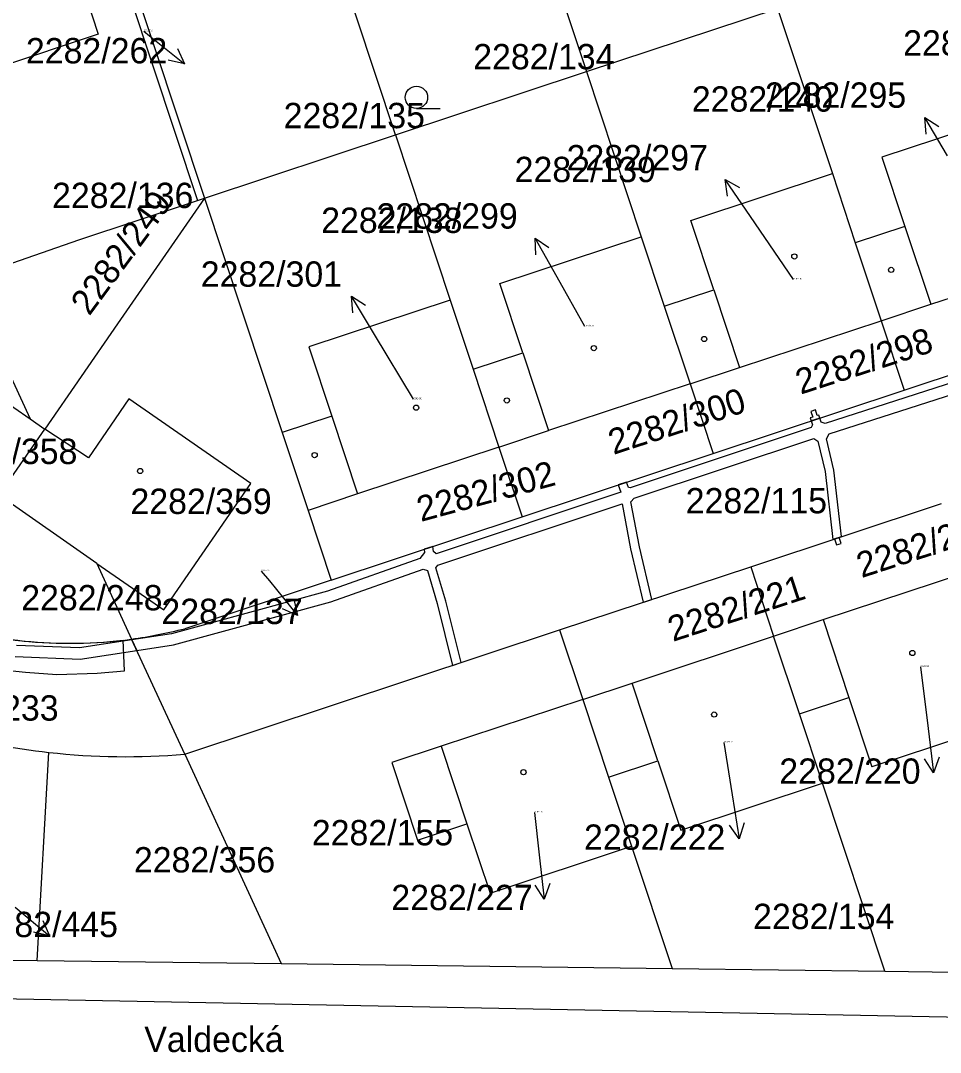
# Model space of a CAD drawing. Extents: x -785744 to -782822, y -1067550 to -1063910.
# Drawn here: x -783802 to -783740.2, y -1066179 to -1066109.7 of the extents above; entities that cross this region are included whole.
import ezdxf

# ---------------------------------------------------------------- set-up
doc = ezdxf.new("R2010")
doc.units = 0
for name, color, linetype in [('Hranice parcel', 7, 'Continuous'), ('Parcelní čísla', 7, 'Continuous'), ('Pop_ČP_popisy', 7, 'Continuous'), ('Vnitřní kresba', 7, 'Continuous'), ('Věcná břemena k části', 7, 'Continuous'), ('Značky budov', 7, 'Continuous'), ('Značky kultur', 7, 'Continuous')]:
    doc.layers.add(name, color=color, linetype=linetype)

msp = doc.modelspace()

# ---------------------------------------------------------------- linework, layer by layer
at = {"layer": 'Hranice parcel'}
for p, q in [((-783798.58, -1066096.16), (-783790.08, -1066121.79)), ((-783767.98, -1066101.08), (-783763.99, -1066113.13)), ((-783799.66, -1066101.8), (-783796.75, -1066110.63)), ((-783751.17, -1066108.89), (-783747.49, -1066119.98)), ((-783796.75, -1066110.63), (-783806.14, -1066113.74)), ((-783763.99, -1066113.13), (-783760.31, -1066124.22)), ((-783734.68, -1066115.74), (-783744.16, -1066118.88)), ((-783744.16, -1066118.88), (-783742.62, -1066123.53)), ((-783756.98, -1066123.12), (-783747.49, -1066119.98)), ((-783798.05, -1066124.42), (-783790.08, -1066121.79)), ((-783789.61, -1066121.63), (-783795.45, -1066130.06)), ((-783790.08, -1066121.79), (-783789.61, -1066121.63)), ((-783789.61, -1066121.63), (-783784.4, -1066137.36)), ((-783755.44, -1066127.77), (-783756.98, -1066123.12)), ((-783769.8, -1066127.36), (-783760.31, -1066124.22)), ((-783805.49, -1066127), (-783798.05, -1066124.42)), ((-783740.89, -1066128.75), (-783731.4, -1066125.61)), ((-783805.65, -1066127.05), (-783801.32, -1066136.44)), ((-783768.26, -1066132.01), (-783769.8, -1066127.36)), ((-783758.77, -1066128.87), (-783755.44, -1066127.77)), ((-783773.13, -1066128.47), (-783782.62, -1066131.61)), ((-783744.22, -1066129.85), (-783740.89, -1066128.75)), ((-783753.72, -1066132.99), (-783744.22, -1066129.85)), ((-783795.45, -1066130.06), (-783800.34, -1066137.12)), ((-783808.56, -1066131.43), (-783801.32, -1066136.44)), ((-783782.62, -1066131.61), (-783781.08, -1066136.26)), ((-783771.59, -1066133.11), (-783768.26, -1066132.01)), ((-783757.04, -1066134.09), (-783753.72, -1066132.99)), ((-783794.7, -1066135.1), (-783797.41, -1066139.05)), ((-783786.52, -1066140.78), (-783794.7, -1066135.1)), ((-783801.32, -1066136.44), (-783800.34, -1066137.12)), ((-783781.08, -1066136.26), (-783784.4, -1066137.36)), ((-783797.41, -1066139.05), (-783800.34, -1066137.12)), ((-783784.4, -1066137.36), (-783782.67, -1066142.58)), ((-783769.86, -1066138.33), (-783766.53, -1066137.23)), ((-783769.86, -1066138.33), (-783779.35, -1066141.48)), ((-783792.36, -1066149.26), (-783786.52, -1066140.78)), ((-783779.35, -1066141.48), (-783782.67, -1066142.58)), ((-783782.67, -1066142.58), (-783781.12, -1066147.26)), ((-783796.85, -1066146.14), (-783792.36, -1066149.26)), ((-783796.85, -1066146.14), (-783794.51, -1066151.22)), ((-783752.97, -1066146.36), (-783751.43, -1066151.02)), ((-783748.11, -1066149.91), (-783738.62, -1066146.77)), ((-783751.43, -1066151.02), (-783748.11, -1066149.91)), ((-783765.79, -1066150.6), (-783764.24, -1066155.27)), ((-783760.92, -1066154.17), (-783751.43, -1066151.02)), ((-783764.24, -1066155.27), (-783760.92, -1066154.17)), ((-783764.24, -1066155.27), (-783773.74, -1066158.4)), ((-783749.7, -1066156.24), (-783746.38, -1066155.14)), ((-783746.38, -1066155.14), (-783744.84, -1066159.79)), ((-783735.34, -1066156.64), (-783744.84, -1066159.79)), ((-783800.85, -1066172.79), (-783800.06, -1066158.82)), ((-783773.74, -1066158.4), (-783777.06, -1066159.5)), ((-783777.06, -1066159.5), (-783775.33, -1066164.72)), ((-783762.51, -1066160.49), (-783759.19, -1066159.39)), ((-783759.19, -1066159.39), (-783757.65, -1066164.04)), ((-783762.51, -1066160.49), (-783760.97, -1066165.12)), ((-783757.65, -1066164.04), (-783748.15, -1066160.89)), ((-783775.33, -1066164.72), (-783772.01, -1066163.62)), ((-783772.01, -1066163.62), (-783770.46, -1066168.27)), ((-783770.46, -1066168.27), (-783760.97, -1066165.12)), ((-783760.97, -1066165.12), (-783758.25, -1066173.33)), ((-783809.16, -1066172.69), (-783800.85, -1066172.79)), ((-783800.85, -1066172.79), (-783784.47, -1066173))]:
    msp.add_line(p, q, dxfattribs=at)
for points in [[(-783776.8, -1066117.38), (-783780.79, -1066105.33)], [(-783794.8, -1066105.97), (-783789.61, -1066121.63)], [(-783763.99, -1066113.13), (-783751.17, -1066108.89)], [(-783776.8, -1066117.38), (-783763.99, -1066113.13)], [(-783789.61, -1066121.63), (-783776.8, -1066117.38)], [(-783776.8, -1066117.38), (-783773.13, -1066128.47)], [(-783747.49, -1066119.98), (-783745.95, -1066124.63)], [(-783742.62, -1066123.53), (-783745.95, -1066124.63)], [(-783760.31, -1066124.22), (-783758.77, -1066128.87)], [(-783745.95, -1066124.63), (-783744.22, -1066129.85)], [(-783773.13, -1066128.47), (-783771.59, -1066133.11)], [(-783758.77, -1066128.87), (-783757.04, -1066134.09)], [(-783744.22, -1066129.85), (-783742.68, -1066134.51)], [(-783742.68, -1066134.51), (-783729.86, -1066130.27)], [(-783771.59, -1066133.11), (-783769.86, -1066138.33)], [(-783757.04, -1066134.09), (-783766.53, -1066137.23)], [(-783757.04, -1066134.09), (-783755.49, -1066138.76)], [(-783755.49, -1066138.76), (-783742.68, -1066134.51)], [(-783803.42, -1066141.57), (-783800.34, -1066137.12)], [(-783769.86, -1066138.33), (-783768.31, -1066143.01)], [(-783768.31, -1066143.01), (-783755.49, -1066138.76)], [(-783796.85, -1066146.14), (-783803.42, -1066141.57)], [(-783752.97, -1066146.36), (-783740.16, -1066142.11)], [(-783781.12, -1066147.26), (-783768.31, -1066143.01)], [(-783765.79, -1066150.6), (-783752.97, -1066146.36)], [(-783781.12, -1066147.26), (-783790.95, -1066150.52)], [(-783790.95, -1066158.94), (-783765.79, -1066150.6)], [(-783790.95, -1066158.94), (-783794.51, -1066151.22)], [(-783749.7, -1066156.24), (-783751.43, -1066151.02)], [(-783764.24, -1066155.27), (-783762.51, -1066160.49)], [(-783748.15, -1066160.89), (-783749.7, -1066156.24)], [(-783790.95, -1066158.94), (-783784.47, -1066173)], [(-783743.97, -1066173.51), (-783748.15, -1066160.89)], [(-783784.47, -1066173), (-783758.25, -1066173.33)], [(-783758.25, -1066173.33), (-783743.97, -1066173.51)], [(-783743.97, -1066173.51), (-783729.69, -1066173.7)]]:
    msp.add_lwpolyline(points, dxfattribs=at)
for centre, radius, start, end in [((-783798.661, -1066120.621), 30.88, 250.33942, 277.72462), ((-783798.951, -1066119.231), 32.296, 277.90404, 284.34418), ((-783795.052, -1066113.226), 45.868, 254.70698, 263.73185), ((-783794.904, -1066113.24), 45.871, 263.54595, 274.9447)]:
    msp.add_arc(centre, radius, start, end, dxfattribs=at)
at = {"layer": 'Pop_ČP_popisy'}
for p, q in [((-783793.31, -1066110.73), (-783790.972, -1066112.61)), ((-783739.76, -1066118.79), (-783741.283, -1066116.205)), ((-783752.99, -1066122.85), (-783754.69, -1066120.378)), ((-783765.96, -1066126.93), (-783767.436, -1066124.318)), ((-783778.21, -1066130.78), (-783779.758, -1066128.21)), ((-783785.27, -1066147.31), (-783783.376, -1066149.636)), ((-783741.07, -1066157.21), (-783740.698, -1066160.187)), ((-783754.21, -1066161.66), (-783753.738, -1066164.623)), ((-783767.16, -1066165.69), (-783766.837, -1066168.673)), ((-783802.32, -1066169.22), (-783800.013, -1066171.138))]:
    msp.add_line(p, q, dxfattribs=at)
for points in [[(-783793.69, -1066110.42), (-783793.31, -1066110.73)], [(-783791.438, -1066111.593), (-783790.972, -1066112.61), (-783792.065, -1066112.373)], [(-783741.206, -1066117.321), (-783741.283, -1066116.205), (-783740.345, -1066116.813)], [(-783754.535, -1066121.485), (-783754.69, -1066120.378), (-783753.711, -1066120.919)], [(-783750.09, -1066127.08), (-783752.99, -1066122.85)], [(-783767.379, -1066125.435), (-783767.436, -1066124.318), (-783766.509, -1066124.943)], [(-783764.1, -1066130.23), (-783765.96, -1066126.93)], [(-783779.67, -1066129.325), (-783779.758, -1066128.21), (-783778.814, -1066128.809)], [(-783775.59, -1066135.12), (-783778.21, -1066130.78)], [(-783785.81, -1066146.65), (-783785.27, -1066147.31)], [(-783783.619, -1066148.545), (-783783.376, -1066149.636), (-783784.395, -1066149.177)], [(-783741.58, -1066153.09), (-783741.07, -1066157.21)], [(-783754.77, -1066158.15), (-783754.21, -1066161.66)], [(-783740.326, -1066159.133), (-783740.698, -1066160.187), (-783741.318, -1066159.257)], [(-783767.47, -1066162.85), (-783767.16, -1066165.69)], [(-783753.401, -1066163.556), (-783753.738, -1066164.623), (-783754.389, -1066163.714)], [(-783766.447, -1066167.624), (-783766.837, -1066168.673), (-783767.441, -1066167.732)], [(-783800.462, -1066170.114), (-783800.013, -1066171.138), (-783801.102, -1066170.883)]]:
    msp.add_lwpolyline(points, dxfattribs=at)
at = {"layer": 'Vnitřní kresba'}
for p, q in [((-783742.62, -1066123.53), (-783740.89, -1066128.75)), ((-783755.44, -1066127.77), (-783753.72, -1066132.99)), ((-783768.26, -1066132.01), (-783766.53, -1066137.23)), ((-783781.08, -1066136.26), (-783779.35, -1066141.48)), ((-783748.11, -1066149.91), (-783746.38, -1066155.14)), ((-783759.19, -1066159.39), (-783760.92, -1066154.17)), ((-783773.74, -1066158.4), (-783772.01, -1066163.62))]:
    msp.add_line(p, q, dxfattribs=at)
msp.add_lwpolyline([(-783809.2, -1066175.23), (-783729.43, -1066176.78)], dxfattribs=at)
at = {"layer": 'Věcná břemena k části'}
for points in [[(-783736.52, -1066133.06), (-783747.98, -1066136.75)], [(-783747.71, -1066137.45), (-783736.34, -1066133.79)], [(-783748.63, -1066135.83), (-783748.93, -1066135.94)], [(-783748.93, -1066135.94), (-783748.8, -1066136.32)], [(-783748.5, -1066136.21), (-783748.63, -1066135.83)], [(-783748.8, -1066136.32), (-783748.98, -1066136.38)], [(-783748.98, -1066136.38), (-783748.91, -1066136.58)], [(-783748.91, -1066136.58), (-783748.34, -1066136.39)], [(-783748.34, -1066136.39), (-783748.91, -1066136.58)], [(-783748.91, -1066136.58), (-783748.82, -1066136.85)], [(-783748.4, -1066136.18), (-783748.5, -1066136.21)], [(-783748.34, -1066136.39), (-783748.4, -1066136.18)], [(-783748.25, -1066136.65), (-783748.34, -1066136.39)], [(-783747.98, -1066136.75), (-783748.25, -1066136.65)], [(-783748.92, -1066137.02), (-783761.05, -1066141.06)], [(-783748.82, -1066136.85), (-783748.92, -1066137.02)], [(-783747.88, -1066137.78), (-783747.71, -1066137.45)], [(-783760.8, -1066141.77), (-783748.74, -1066137.75)], [(-783748.74, -1066137.75), (-783748.46, -1066137.93)], [(-783748.46, -1066137.93), (-783747.98, -1066139.98)], [(-783747.39, -1066139.88), (-783747.88, -1066137.78)], [(-783747.98, -1066139.98), (-783747.46, -1066144.53)], [(-783746.88, -1066144.34), (-783747.39, -1066139.88)], [(-783761.3, -1066140.68), (-783761.87, -1066140.87)], [(-783761.87, -1066140.87), (-783761.68, -1066141.36)], [(-783761.16, -1066141.05), (-783761.3, -1066140.68)], [(-783761.68, -1066141.36), (-783774.08, -1066145.5)], [(-783761.05, -1066141.06), (-783761.16, -1066141.05)], [(-783773.97, -1066146.26), (-783761.6, -1066142.13)], [(-783761.6, -1066142.13), (-783761.03, -1066145.16)], [(-783761.01, -1066142), (-783760.8, -1066141.77)], [(-783760.44, -1066145.03), (-783761.01, -1066142)], [(-783747.46, -1066144.53), (-783746.88, -1066144.34)], [(-783747.04, -1066144.39), (-783747.35, -1066144.49)], [(-783746.91, -1066144.8), (-783747.04, -1066144.39)], [(-783774.3, -1066145), (-783774.88, -1066145.19)], [(-783774.25, -1066145.34), (-783774.3, -1066145)], [(-783759.61, -1066148.56), (-783760.44, -1066145.03)], [(-783747.35, -1066144.49), (-783747.22, -1066144.9)], [(-783747.22, -1066144.9), (-783746.91, -1066144.8)], [(-783775.18, -1066145.82), (-783781.37, -1066148.01)], [(-783774.85, -1066145.4), (-783775.18, -1066145.82)], [(-783774.88, -1066145.19), (-783774.85, -1066145.4)], [(-783774.08, -1066145.5), (-783774.25, -1066145.34)], [(-783761.03, -1066145.16), (-783760.19, -1066148.75)], [(-783774.09, -1066146.43), (-783773.97, -1066146.26)], [(-783773.43, -1066148.67), (-783774.09, -1066146.43)], [(-783781.14, -1066148.72), (-783774.95, -1066146.53)], [(-783774.95, -1066146.53), (-783774.66, -1066146.62)], [(-783774.66, -1066146.62), (-783774.01, -1066148.83)], [(-783781.37, -1066148.01), (-783791.84, -1066150.86)], [(-783760.08, -1066148.71), (-783759.61, -1066148.56)], [(-783791.69, -1066151.6), (-783781.14, -1066148.72)], [(-783774.01, -1066148.83), (-783772.97, -1066152.98)], [(-783772.4, -1066152.79), (-783773.43, -1066148.67)], [(-783760.19, -1066148.75), (-783760.08, -1066148.71)], [(-783806.6, -1066152.58), (-783803.14, -1066153.28), (-783801.64, -1066153.44), (-783799.52, -1066153.6), (-783796.83, -1066153.5), (-783795, -1066153.34), (-783795.08, -1066151.29)], [(-783794.49, -1066151.27), (-783798.01, -1066151.81)], [(-783791.84, -1066150.86), (-783794.49, -1066151.27)], [(-783794.16, -1066151.98), (-783794.49, -1066151.27)], [(-783794.49, -1066151.27), (-783794.16, -1066151.98)], [(-783798.01, -1066151.81), (-783802.23, -1066151.64)], [(-783797.96, -1066152.56), (-783794.16, -1066151.98)], [(-783794.16, -1066151.98), (-783791.69, -1066151.6)], [(-783802.33, -1066152.39), (-783797.96, -1066152.56)], [(-783772.97, -1066152.98), (-783772.4, -1066152.79)]]:
    msp.add_lwpolyline(points, dxfattribs=at)
msp.add_arc((-783798.669, -1066120.659), 30.84, 250.33031, 276.68329, dxfattribs=at)
at = {"layer": 'Značky budov'}
for centre in [(-783750.04, -1066125.54), (-783743.55, -1066126.44), (-783756.09, -1066131.08), (-783763.5, -1066131.69), (-783769.33, -1066135.2), (-783775.42, -1066135.69), (-783782.23, -1066138.87), (-783793.94, -1066139.94), (-783742.12, -1066152.15), (-783755.42, -1066156.28), (-783768.22, -1066160.15)]:
    msp.add_circle(centre, 0.175, dxfattribs=at)
at = {"layer": 'Značky kultur'}
msp.add_line((-783775.4, -1066115.61), (-783773.8, -1066115.61), dxfattribs=at)
msp.add_circle((-783775.4, -1066114.86), 0.75, dxfattribs=at)

# ---------------------------------------------------------------- texts
at = {"layer": 'Parcelní čísla'}
for s, height, p in [('2282/262', 0.1, (-783793.69, -1066110.42)), ('2282/141', 1.7, (-783742.74, -1066112.06)), ('2282/134', 1.7, (-783771.59, -1066112.98)), ('2282/140', 1.7, (-783756.92, -1066115.82)), ('2282/135', 1.7, (-783784.31, -1066116.93)), ('2282/139', 1.7, (-783768.81, -1066120.55)), ('2282/136', 1.7, (-783799.85, -1066122.29)), ('2282/138', 1.7, (-783781.79, -1066123.96)), ('2282/297', 0.1, (-783750.09, -1066127.08)), ('2282/299', 0.1, (-783764.1, -1066130.23)), ('2282/301', 0.1, (-783775.59, -1066135.12)), ('2282/358', 1.7, (-783807.63, -1066139.47)), ('2282/359', 1.7, (-783794.59, -1066142.82)), ('2282/115', 1.7, (-783757.33, -1066142.78)), ('2282/137', 0.1, (-783785.81, -1066146.65)), ('2282/248', 1.7, (-783801.92, -1066149.29)), ('2282/220', 0.1, (-783741.58, -1066153.09)), ('2282/222', 0.1, (-783754.77, -1066158.15)), ('2282/227', 0.1, (-783767.47, -1066162.85)), ('2282/155', 1.7, (-783782.42, -1066165.06)), ('2282/356', 1.7, (-783794.36, -1066166.88)), ('2282/154', 1.7, (-783752.81, -1066170.68))]:
    msp.add_text(s, height=height, dxfattribs=at).set_placement(p)
for s, rotation, p in [('2282/249', 53.63406, (-783797.35, -1066129.58)), ('2282/298', 18, (-783749.62, -1066134.82)), ('2282/300', 18, (-783762.18, -1066138.86)), ('2282/302', 15.3, (-783775.1, -1066143.36)), ('2282/219', 18, (-783745.53, -1066147.13)), ('2282/221', 18, (-783758.19, -1066151.41))]:
    msp.add_text(s, height=1.7, rotation=rotation, dxfattribs=at).set_placement(p)
at = {"layer": 'Pop_ČP_popisy'}
for s, p in [('2282/262', (-783801.605, -1066112.58)), ('2282/295', (-783752.018, -1066115.56)), ('2282/297', (-783765.324, -1066119.76)), ('2282/299', (-783778.085, -1066123.67)), ('2282/301', (-783789.872, -1066127.57)), ('2282/137', (-783792.513, -1066150.21)), ('2282/233', (-783808.892, -1066156.69)), ('2282/220', (-783751.052, -1066160.93)), ('2282/222', (-783764.155, -1066165.36)), ('2282/227', (-783777.084, -1066169.41)), ('2282/445', (-783804.908, -1066171.22)), ('Valdecká', (-783793.66, -1066178.93))]:
    msp.add_text(s, height=1.7, dxfattribs=at).set_placement(p)

doc.saveas('drawing.dxf')
